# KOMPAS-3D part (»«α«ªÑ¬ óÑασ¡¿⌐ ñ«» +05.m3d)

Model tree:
1. Эскиз:1
2. Операция выдавливания:1
     Расстояние 1 = 8
3. Эскиз:2
4. Операция выдавливания:2
     Расстояние 1 = 1
5. Эскиз:3
6. Операция выдавливания:3
     Расстояние 1 = 2.5; Угол 1 = 8
7. Эскиз:4
8. Вырезать элемент выдавливания:1
     Расстояние 1 = 20
9. Эскиз:5
10. Вырезать элемент выдавливания:2
     Расстояние 1 = 3; Угол 1 = 19
11. Скругление:1
     Радиус = 1
12. Скругление:2
     Радиус = 1
13. Скругление:3
     Радиус = 1
14. Эскиз:6
15. Эскиз:7
16. Вырезать элемент выдавливания:3
     Расстояние 1 = 2.5
17. Эскиз:8
18. Вырезать элемент выдавливания:4
     Расстояние 1 = 42
19. Операция выдавливания:4
     Расстояние 1 = 0.8; Расстояние 2 = 1.5
20. Операция выдавливания:5
     Расстояние 1 = 0.5
